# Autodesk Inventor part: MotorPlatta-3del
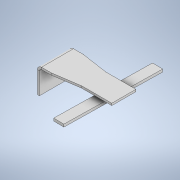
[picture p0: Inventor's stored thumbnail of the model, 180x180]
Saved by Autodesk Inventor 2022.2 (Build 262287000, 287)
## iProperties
Created: 2022-03
Part Number: MotorPlatta-3del
Material: Generic
Document SubType Name: Sheet Metal
Designer: cl
Density: 1 g/cm^3
Sheet Metal Rule: Default
Appearance: Default
Author: cl
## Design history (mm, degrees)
node "Face1"
  sketch "Sketch1"
    geometry: L1 (0, 0)-(0, -186); L2 (0, -186)-(-80, -186); L3 (-80, -186)-(-235, -163); L4 (-235, -163)-(-410, -163); L5 (-410, -163)-(-410, -23); L6 (-410, -23)-(-235, -23); L7 (-235, -23)-(-80, 0); L8 (-80, 0)-(0, 0)
    constraints: 16 end point, 3 perpendicular, 1 horizontal, 1 parallel, 1 vertical
    dimensions: "d0" = 186 distance of L1.start L1.end; "d1" = 80 distance of L1.end L2.end; "d2" = 175 distance of L3.end L4.end; "d3" = 140 distance of L4.end L5.end; "d4" = 23 distance between parallel lines of L2 L4; "d5" = 80 distance from line of L1 L7.end; "d6" = 410 distance between parallel lines of L1 L5; "d7" = 175 distance of L5.end L6.end
node "Flange1"
sketch "Sketch3"
  geometry: L1 (235, -163)-(410, -163) reference; L2 (410, -163)-(410, -23) reference; C1 r 15 at (318, -93); 1 further point
  constraints: 1 centre point
  dimensions: "d19" = 30 diameter of C1; "d20" = 70 distance from line of L1 C1.centre; "d21" = 92 distance from line of L2 C1.centre
extrude "Extrusion1" join sketch "Sketch3" distance "d22" = 28; taper "d23" = 0 deg
sketch "Sketch4"
  geometry: L1 (-32.161, -291.047)-(-42.022, 273.867); L2 (-318, 93)-(-318, -93) reference; L3 (-32.161, -291.047)-(27.83, -290); L4 (27.83, -290)-(17.969, 274.914); L5 (17.969, 274.914)-(-42.022, 273.867); L6 (-83, -70)-(92, -70) reference; L7 (92, -70)-(92, 70) reference
  constraints: 8 end point, 3 perpendicular
  dimensions: "d24" = 1 deg angle of L2 L1; "d25" = 565 distance of L1.start L1.end; "d26" = 60 distance of L1.start L3.end; "d27" = 68 distance from line of L4 L6.end; "d28" = 220 vertical distance of L6.end L3.end
extrude "Extrusion2" join sketch "Sketch4" distance "d29" = 15; taper "d30" = 0 deg
sketch "Sketch5"
  geometry: L1 (17.969, 274.914)-(-42.022, 273.867) reference; L2 (-42.022, 273.867)-(-32.161, -291.047) reference; L3 (-32.161, -291.047)-(27.83, -290) reference; L4 (27.83, -290)-(17.969, 274.914) reference; C1 r 6 at (12.57, -275.264); C2 r 6 at (-26.762, 259.131); 1 further point
  constraints: 2 centre point
  dimensions: "d31" = 12 diameter of C1; "d32" = 15 distance from line of L4 C1.centre; "d33" = 15 distance from line of L3 C1.centre; "d34" = 12 diameter of C2; "d35" = 15 distance from line of L2 C2.centre; "d36" = 15 distance from line of L1 C2.centre
extrude "Extrusion3" join sketch "Sketch5" distance "d37" = 10; taper "d38" = 0 deg
body "Solid1"
face "Plate1" dims "d8" = 12 (= Thickness)
sketch "Sketch2"
  geometry: L1 through (0, 93) direction (0, -1); L2 through (75, 0) direction (1, 0); L3 (150, 0)-(150, 186); L4 (150, 186)-(0, 186)
  constraints: 6 end point, 1 horizontal, 1 perpendicular, 1 vertical
face "Plate2" dims "d8" = 12 (= Thickness), "d9" = 12 (= BendReliefWidth), "d10" = 6 (= BendReliefDepth), "d11" = 24 (= MinimumRemnant), "d12" = 12 (= TransitionRadius), "d13" = 150, "d14" = 90 deg, "d15" = 12 (= BendRadius), "d16" = 48 (= CornerReliefSize), "d17" = 12 (= GapSize), "d18" = 12 (= JacobiRadiusSize), "SeamGap" = 0.01
bend "Bend1" dims "d8" = 12 (= Thickness), "d9" = 12 (= BendReliefWidth), "d10" = 6 (= BendReliefDepth), "d11" = 24 (= MinimumRemnant), "d12" = 12 (= TransitionRadius), "d13" = 150, "d14" = 90 deg, "d15" = 12 (= BendRadius), "SeamGap" = 0.01
feature "Corner1" dims "d13" = 150, "d14" = 90 deg, "d16" = 48 (= CornerReliefSize), "d17" = 12 (= GapSize), "d18" = 12 (= JacobiRadiusSize)
node "Projected Loop1"
other parameters: "Thickness" = 12 (derived), "KFactor" = 4.4, "BendRadius" = 12 (= Thickness), "BendReliefWidth" = 12 (= Thickness), "BendReliefDepth" = 6 (= 0.5 x Thickness), "CornerReliefSize" = 48 (= 4 x Thickness), "MinimumRemnant" = 24 (= 2 x Thickness), "TransitionRadius" = 12 (= BendRadius), "JacobiRadiusSize" = 12 (= BendRadius), "GapSize" = 12 (= Thickness)
